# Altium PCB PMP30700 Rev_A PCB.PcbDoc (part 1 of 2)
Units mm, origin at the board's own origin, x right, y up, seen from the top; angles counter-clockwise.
Board outline 118.11 x 43.81 mm, 4 copper layers (Top Layer, Layer 1, Layer 2, Bottom Layer), stack 1.786 mm thick; 113 components, 51 nets, 253 pads, 184 vias.
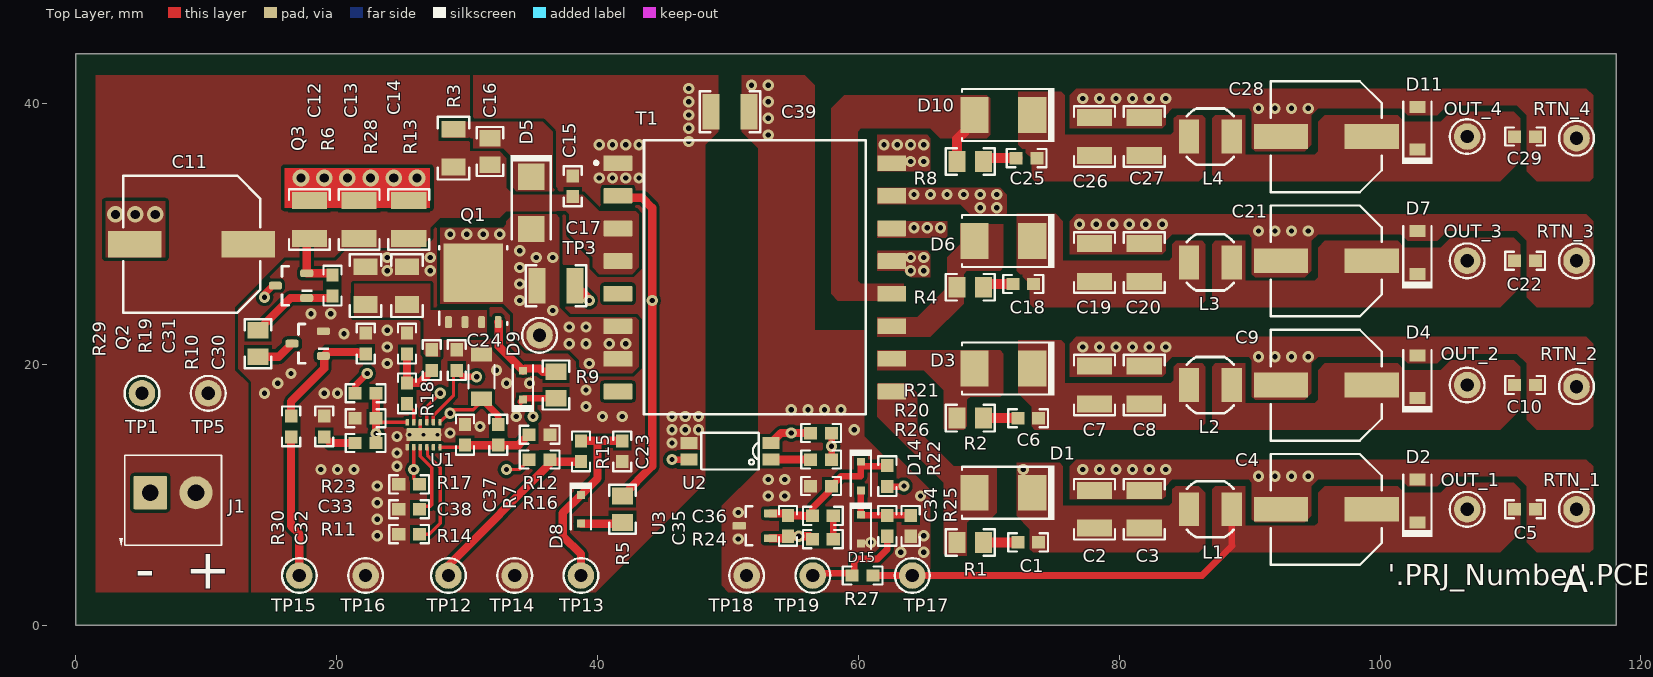
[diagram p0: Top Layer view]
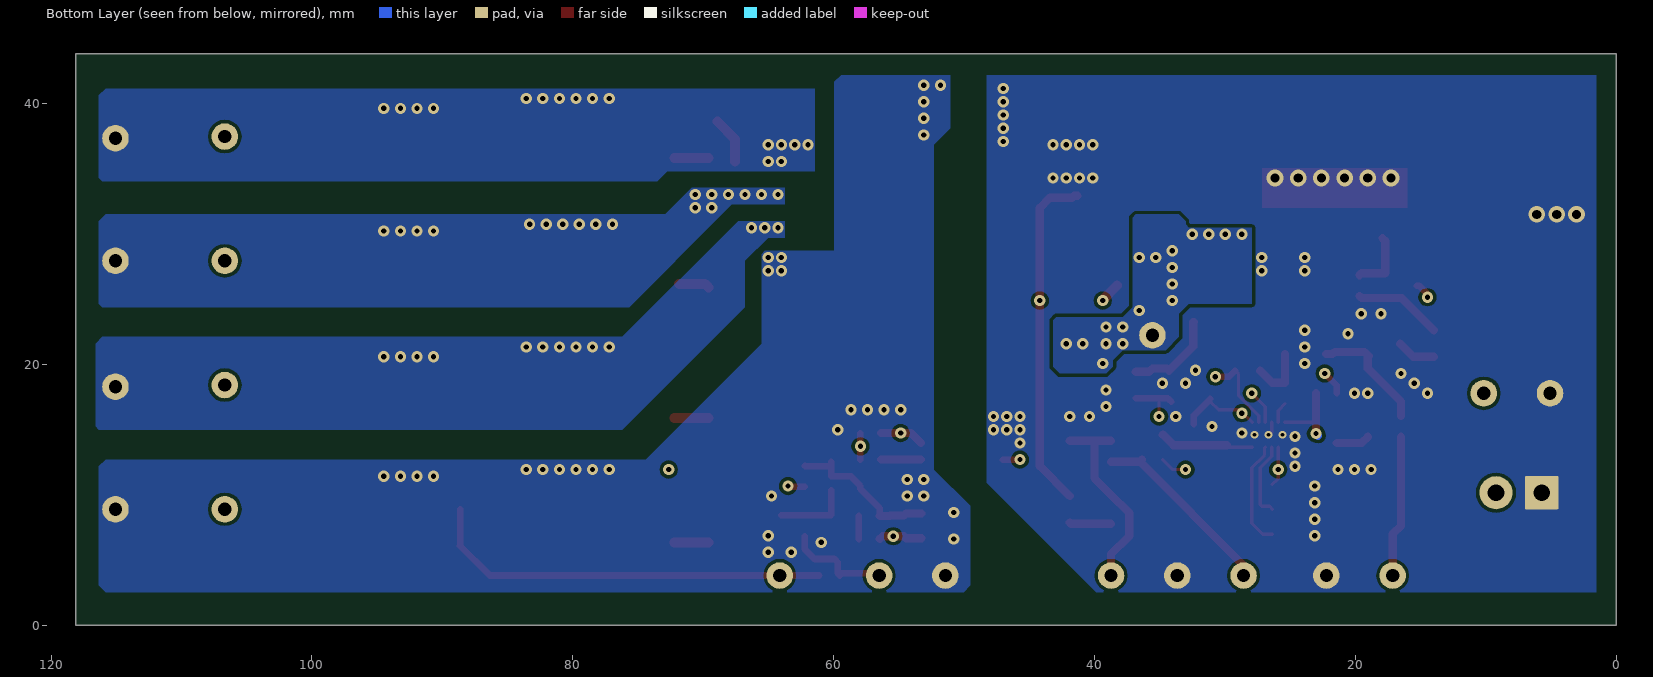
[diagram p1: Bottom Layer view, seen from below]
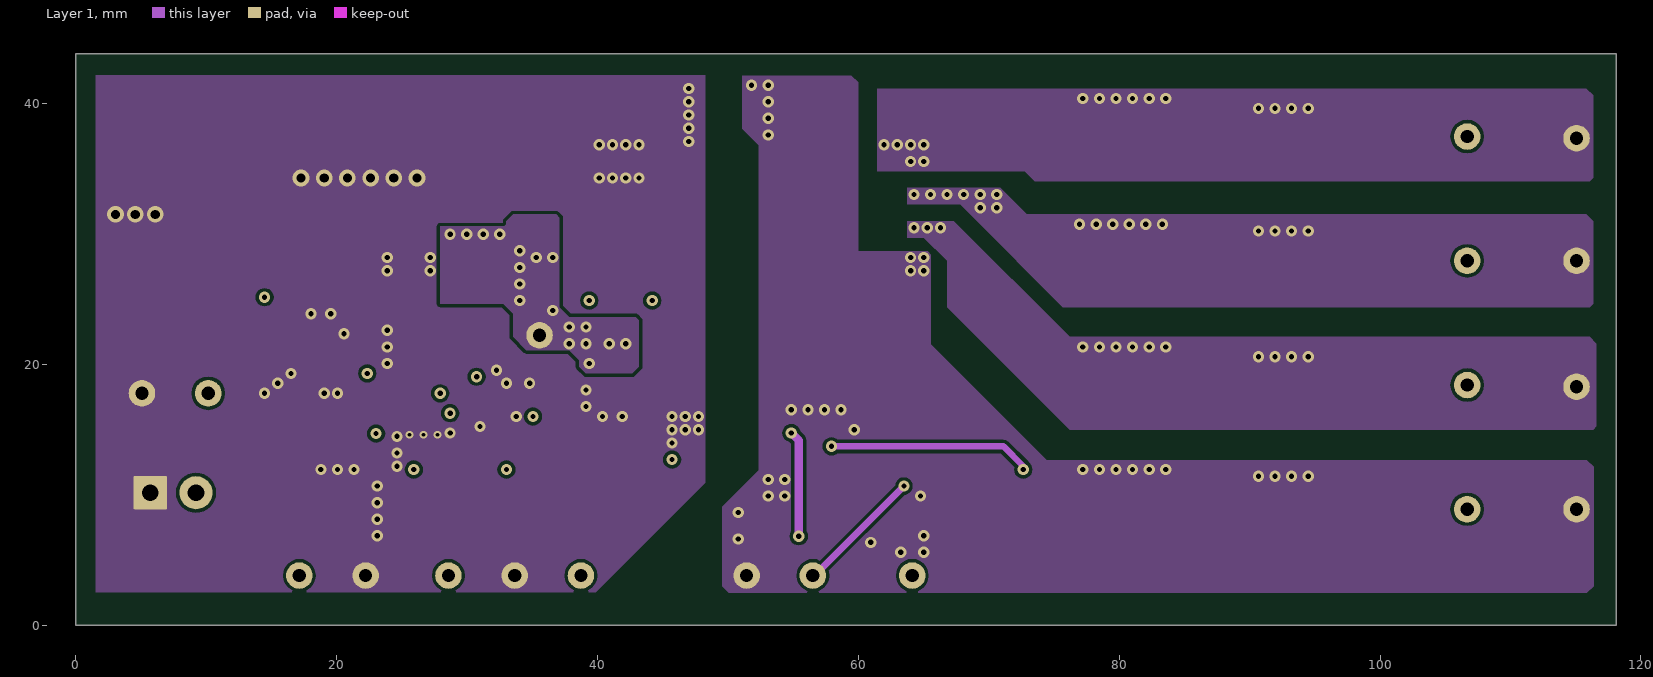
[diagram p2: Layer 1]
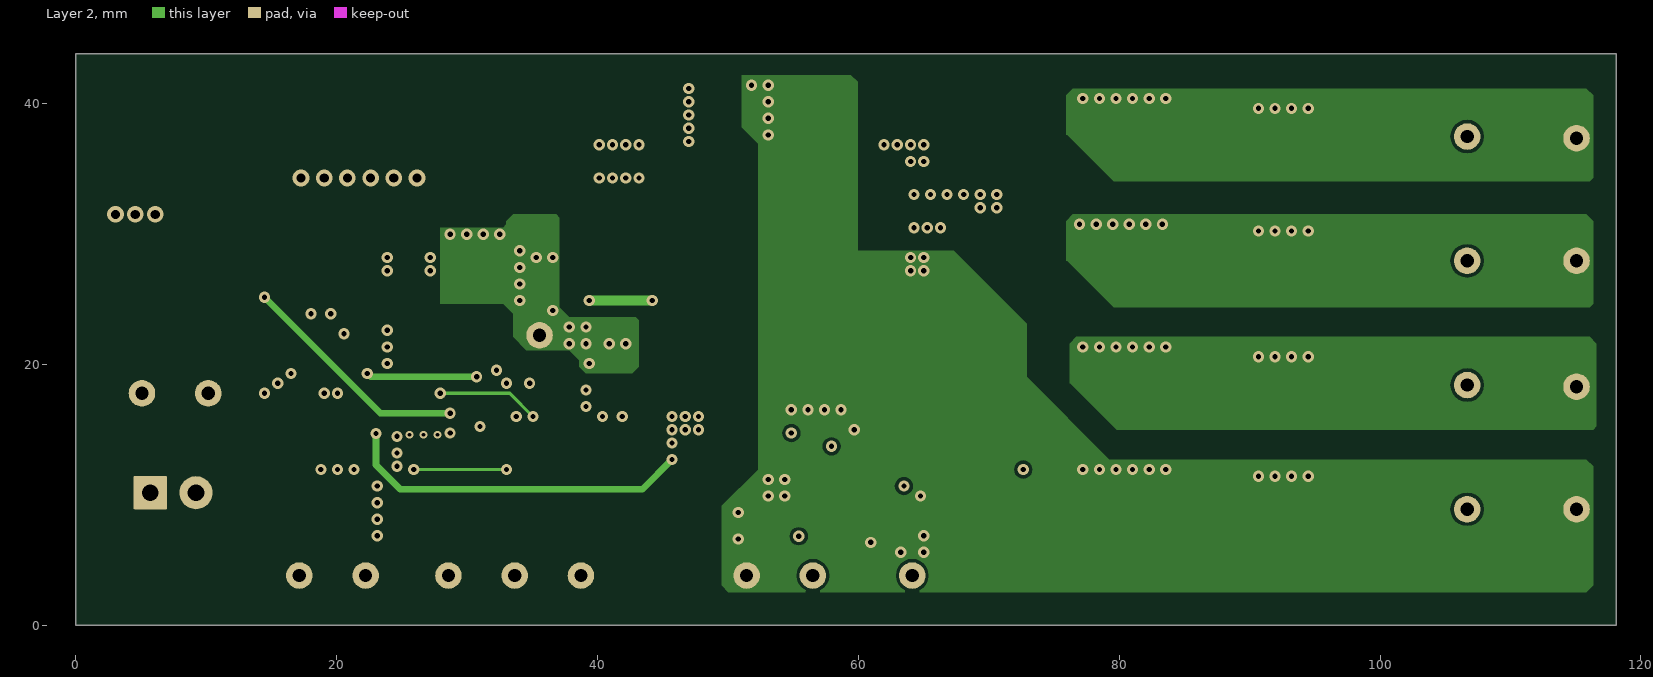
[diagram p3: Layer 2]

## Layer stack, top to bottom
Top Solder: solder mask 0.0102, Solder Resist, Dk 3.5
Top Layer: signal copper 0.035
Dielectric 1: prepreg 0.0711, PP-006, Dk 4.1
Layer 1: signal copper 0.035
Dielectric1: core 1.5037, FR-4, Dk 4.8
Layer 2: signal copper 0.035
Dielectric 2: prepreg 0.0711, PP-006, Dk 4.1
Bottom Layer: signal copper 0.035
Bottom Solder: solder mask 0.0102, Solder Resist, Dk 3.5

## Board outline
0,0 118.11,0 118.11,43.815 0,43.815

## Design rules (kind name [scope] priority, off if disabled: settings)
AcuteAngle [All] p1: minimum=4.50000000000000E+0001 checktracksonly=FALSE
AssemblyTestPointUsage [All] p1: valid=2
BoardOutlineClearance BoardOutlineClearance_MountingHoles [OnCopper and InComponentClass('Mounting Holes')] p1: gap=1.016 ignorepadtopadclearanceinfootprint=FALSE
BoardOutlineClearance BoardOutlineClearance_Poly [OnCopper and IsPoly] p2: gap=0.635 ignorepadtopadclearanceinfootprint=FALSE
BoardOutlineClearance [OnCopper and Not InComponentClass('Logo') and not InComponentClass('FiducialMark') and not InRegion(1000,500,4000,800) and not InPoly] p3: gap=1.905 ignorepadtopadclearanceinfootprint=FALSE
Clearance Clearance_Keepouts [((IsTrack Or IsArc) And Not InPoly) And IsFree and IsKeepOut vs ((IsTrack Or IsArc) And Not InPoly) And IsFree and IsKeepOut] p1: gap=0 ignorepadtopadclearanceinfootprint=FALSE
Clearance Clearance_Poly [InPolygon] p2: gap=0.254 ignorepadtopadclearanceinfootprint=FALSE
Clearance Clearance_FiducialMark [IsKeepOut and InComponentClass('FiducialMark') vs IsPad and InComponentClass('FiducialMark')] p3: gap=0 ignorepadtopadclearanceinfootprint=FALSE
Clearance [All] p4: gap=0.2 ignorepadtopadclearanceinfootprint=FALSE except(0: Arc-Hole Track-Hole SMDPad-Hole THPad-Hole Via-Hole Fill-Hole Poly-Hole Region-Hole Text-Hole)
ComponentClearance ComponentClearance_MountingHoles_FiducialMarks [InComponentClass('Mounting Holes') vs InComponentClass('FiducialMark')] p1: gap=1.27 collisioncheckmode=3 verticalgap=0.254 showdistances=FALSE
ComponentClearance ComponentClearance_Shunt [InComponentClass('Header') vs InComponentClass('Shunt')] p2: gap=0 collisioncheckmode=3 verticalgap=0 showdistances=FALSE
ComponentClearance ComponentClearance_Logo [InComponentClass('Logo')] p3: gap=1.27 collisioncheckmode=3 verticalgap=0.254 showdistances=FALSE
ComponentClearance ComponentClearance_ScrewToNut [(HasFootprint('NY PMS 440 0025 PH')) vs (HasFootprint('Keystone_1902C'))] p4: gap=0.127 collisioncheckmode=3 verticalgap=0.254 showdistances=FALSE
ComponentClearance ComponentClearance_MountingHoles [InComponentClass('Mounting Holes')] p5: gap=6.35 collisioncheckmode=3 verticalgap=2540 showdistances=FALSE
ComponentClearance ComponentClearance_SmallPassives [HasFootprint('0201*') or HasFootprint('0402*') or HasFootprint('0508') or HasFootprint('0603*') or HasFootprint('0612') or HasFootprint('0805*') or HasFootprint('0815*') or HasFootprint('0830*') or HasFootprint('1206*') or HasFootprint('1210*') or HasFootprint('1808*') or HasFootprint('1812*') or HasFootprint('1825*') or HasFootprint('2010*') or HasFootprint('2220*') or HasFootprint('2225*') or HasFootprint('2512*') or HasFootprint('2728*') or HasFootprint('3518*') vs HasFootprint('0201*') or HasFootprint('0402*') or HasFootprint('0508') or HasFootprint('0603*') or HasFootprint('0612') or HasFootprint('0805*') or HasFootprint('0815*') or HasFootprint('0830*') or HasFootprint('1206*') or HasFootprint('1210*') or HasFootprint('1808*') or HasFootprint('1812*') or HasFootprint('1825*') or HasFootprint('2010*') or HasFootprint('2220*') or HasFootprint('2225*') or HasFootprint('2512*') or HasFootprint('2728*') or HasFootprint('3518*')] p6: gap=0.38 collisioncheckmode=3 verticalgap=0.254 showdistances=FALSE
ComponentClearance ComponentClearance_THtoSMT [IsThruComponent vs IsSMTComponent] p7: gap=1.016 collisioncheckmode=3 verticalgap=0.762 showdistances=FALSE
ComponentClearance ComponentClearance_THtoTH [IsThruComponent vs IsThruComponent] p8: gap=0.762 collisioncheckmode=3 verticalgap=0.762 showdistances=FALSE
ComponentClearance [All] p9: gap=0.762 collisioncheckmode=3 verticalgap=0.254 showdistances=FALSE
DiffPairsRouting [All] p1: maxlimit=2.54 minlimit=0.254 mostfreqgap=0.254 toplayer_minwidth=0.381 toplayer_maxwidth=0.381 toplayer_prefwidth=0.381 midlayer1_minwidth=0.381 midlayer1_maxwidth=0.381 midlayer1_prefwidth=0.381 midlayer2_minwidth=0.381 midlayer2_maxwidth=0.381 midlayer2_prefwidth=0.381 bottomlayer_minwidth=0.381 bottomlayer_maxwidth=0.381 bottomlayer_prefwidth=0.381 maxuncoupledlength=25.4
FabricationTestPointUsage TestPointUsage [All] p1: valid=2 allowmultiple=FALSE
FabricationTestpoint Testpoint [All] p1: side=3 testpointundercomponent=TRUE minsize=1.016 maxsize=2.54 preferedsize=1.524 minholesize=0 maxholesize=1.016 preferedholesize=0.813 testpointgrid=0.025 allowsidetop=TRUE allowsidebottom=TRUE usegrid=TRUE gridtolerance=0
FanoutControl Fanout_LCC [IsLCC] p1: bgadir=Out bgaviamode=Centered fanoutstyle=Auto fanoutdirection=Alternating viagrid=0.025 // Fanout_LCC (Default Rule)
FanoutControl Fanout_BGA [IsBGA] p2: bgadir=Out bgaviamode=Centered fanoutstyle=Auto fanoutdirection=Alternating viagrid=0.025 // Fanout_BGA (Default Rule)
FanoutControl Fanout_Default [All] p4: bgadir=Out bgaviamode=Centered fanoutstyle=Auto fanoutdirection=Alternating viagrid=0.025 // Fanout_Default (Default Rule)
FanoutControl Fanout_Small [(CompPinCount < 5)] p5: bgadir=Out bgaviamode=Centered fanoutstyle=Auto fanoutdirection=OutThenIn viagrid=0.025 // Fanout_Small (Default Rule)
HoleSize [All] p1: absolutevalues=TRUE maxlimit=6.375 minlimit=0.3 maxpercent=80.000 minpercent=20.000
MinimumAnnularRing MinimumAnnularRing_ThermalPadVias [IsVia and InAnyComponent] p1: minimumring=0.15
MinimumAnnularRing [All] p2: minimumring=0.203
MinimumSolderMaskSliver MinimumSolderMaskSliver_Logo [InComponentClass('Logo') vs InComponentClass('Logo')] p1: minsoldermaskwidth=0.018
MinimumSolderMaskSliver [All] p2: minsoldermaskwidth=0.1
PlaneConnect [All] p1: planeconnectstyle=Relief reliefexpansion=0.254 reliefentries=4 reliefconductorwidth=0.254 reliefairgap=0.254
PolygonConnect [All] p1: connectstyle=Direct reliefconductorwidth=0.254 reliefentries=4 polygonreliefangle="90 Angle" airgapwidth=0.254
RoutingVias ThermalPadVias [IsVia and InAnyComponent] p1: holewidth=0.3 width=0.5 viastyle="Through Hole" minholewidth=0.3 minwidth=0.6 maxholewidth=0.5 maxwidth=1
RoutingVias [All] p2: holewidth=0.5 width=0.9 viastyle="Through Hole" minholewidth=0.3 minwidth=0.6 maxholewidth=1.016 maxwidth=1.651
SilkToBoardRegionClearance [Not ((IsComment or IsDesignator) And (Hide <> 'False')) and not InRegion(1000,500,4000,800)] p1:
SilkToSilkClearance SilkToSilkClearance_Pb-FreeLogo [(HasFootprint('Pb-Free_Overlay_Medium') OR HasFootprint('Pb-Free_Overlay_Small')) vs (HasFootprint('Pb-Free_Overlay_Medium') OR HasFootprint('Pb-Free_Overlay_Small'))] p1: silktosilkclearance=0
SilkToSilkClearance [All] p2: silktosilkclearance=0.102
SilkToSolderMaskClearance SilkToComponentPadClearance [(IsPad or IsFill or IsRegion) and InAnycomponent] p1: minsilkscreentomaskgap=0.127 clearancetoexposedcopper=TRUE
SilkToSolderMaskClearance "Silk to Solder Mask Opening" [All] p2: minsilkscreentomaskgap=0.102 clearancetoexposedcopper=FALSE
SolderMaskExpansion [All] p1: expansion=0.05
Width [All] p1: maxlimit=2.54 minlimit=0.152 preferedwidth=0.254 checkconnectedcopper=TRUE
15 further rules are at their usual default settings.

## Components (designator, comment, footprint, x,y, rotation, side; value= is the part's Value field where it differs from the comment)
C1 "GRM188R72A471KA01D" 0603 73.025,6.35 r180 top value=470pF
C2 "GRM32ER71H106KA12L" 1210_270 78.105,8.89 r90 top value=10uF
C3 "GRM32ER71H106KA12L" 1210_270 81.915,8.89 r90 top value=10uF
C4 "25SVPF100M" SVPF_E7 95.885,8.89 r180 top value=100uF
C5 "GCM188R71H104KA57D" 0603 111.125,8.89 r0 top value=0.1uF
C6 "GRM188R72A471KA01D" 0603 73.025,15.875 r180 top value=470pF
C7 "GRM32ER71H106KA12L" 1210_270 78.105,18.415 r90 top value=10uF
C8 "GRM32ER71H106KA12L" 1210_270 81.915,18.415 r90 top value=10uF
C9 "25SVPF100M" SVPF_E7 95.885,18.415 r180 top value=100uF
C10 "GCM188R71H104KA57D" 0603 111.125,18.415 r0 top value=0.1uF
C11 "EEH-ZC1H101P" Panasonic_G 8.89,29.21 r180 top value=100uF
C12 "GRM32ER71H106KA12L" 1210_270 17.915,31.115 r90 top value=10uF
C13 "GRM32ER71H106KA12L" 1210_270 21.725,31.115 r90 top value=10uF
C14 "GRM32ER71H106KA12L" 1210_270 25.535,31.115 r90 top value=10uF
C15 "GCM188R71H104KA57D" 0603 38.1,33.655 r90 top value=0.1uF
C16 "GRM21BR72A103MA01L" 0805_HV 31.75,36.322 r90 top value=0.01uF
C17 "GRM32ER71H106KA12L" 1210_270 36.83,26.035 r0 top value=10uF
C18 "GRM188R72A471KA01D" 0603 72.644,26.162 r180 top value=470pF
C19 "GRM32ER71H106KA12L" 1210_270 78.105,27.813 r90 top value=10uF
C20 "GRM32ER71H106KA12L" 1210_270 81.915,27.813 r90 top value=10uF
C21 "25SVPF100M" SVPF_E7 95.885,27.94 r180 top value=100uF
C22 "GCM188R71H104KA57D" 0603 111.125,27.94 r0 top value=0.1uF
C23 "GRM188R71E105KA12D" 0603 41.91,13.335 r270 top value=1uF
C24 "C3216X7S2A335M160AB" 1206_190 31.115,19.05 r90 top value=3.3uF
C25 "GRM188R72A471KA01D" 0603 72.898,35.814 r180 top value=470pF
C26 "GRM32ER71H106KA12L" 1210_270 78.105,37.465 r90 top value=10uF
C27 "GRM32ER71H106KA12L" 1210_270 81.915,37.465 r90 top value=10uF
C28 "25SVPF100M" SVPF_E7 95.885,37.465 r180 top value=100uF
C29 "GCM188R71H104KA57D" 0603 111.125,37.465 r0 top value=0.1uF
C30 "GRM188R71E105KA12D" 0603 29.21,20.32 r90 top value=1uF
C31 "GRM188R71H221KA01D" 0603 25.4,21.59 r90 top value=220pF
C32 "06033C473JAT2A" 0603 19.05,15.24 r90 top value=0.047uF
C33 "GRM1885C1H471JA01D" 0603 22.225,15.875 r180 top value=470pF
C34 "06033C473JAT2A" 0603 62.23,7.62 r90 top value=0.047uF
C35 "GRM1885C1H471JA01D" 0603 54.61,7.62 r90 top value=470pF
C36 "06033C473JAT2A" 0603 57.277,8.382 r180 top value=0.047uF
C37 "GRM1885C1H471JA01D" 0603 29.845,14.605 r90 top value=470pF
C38 "GCM188R71H104KA57D" 0603 25.565,8.89 r180 top value=0.1uF
C39 "VJ1210Y102KXEAT5Z" 1210 50.165,39.37 r180 top value=1000pF
D1 "STPS3150U" SMB 71.12,10.16 r180 top
D2 "MMSZ5245B-7-F" SOD-123 102.87,9.525 r90 top value=15V
D3 "STPS3150U" SMB 71.12,19.685 r180 top
D4 "MMSZ5245B-7-F" SOD-123 102.87,19.05 r90 top value=15V
D5 "MBRA1H1000T3G" SMA 34.925,32.385 r270 top value=MBRA1H100T3G
D6 "STPS3150U" SMB 71.12,29.464 r180 top
D7 "MMSZ5245B-7-F" SOD-123 102.87,28.575 r90 top value=15V
D8 "PMEG6010CEJ,115" SOD-323F 38.735,8.89 r270 top value=PMEG6010
D9 "PMEG6010CEJ,115" SOD-323F 34.29,18.415 r90 top value=PMEG6010
D10 "STPS3150U" SMB 71.12,39.116 r180 top
D11 "MMSZ5245B-7-F" SOD-123 102.87,38.1 r90 top value=15V
D14 "MMDL914-TP" SOD-323 60.198,11.43 r270 top value=100V
D15 "MMDL914-TP" SOD-323 60.198,7.366 r270 top value=100V
J1 "ED555/2DS" TERM_BLK_ED555-2DS 5.715,10.16 r0 top
L1 "SD43-472MLB" SD43 86.995,8.89 r0 top value=4.7uH
L2 "SD43-472MLB" SD43 86.995,18.415 r0 top value=4.7uH
L3 "SD43-472MLB" SD43 86.995,27.813 r0 top value=4.7uH
L4 "SD43-472MLB" SD43 86.995,37.465 r0 top value=4.7uH
OUT_1 "5000" Keystone5000 106.68,8.89 r0 top
OUT_2 "5000" Keystone5000 106.68,18.415 r0 top
OUT_3 "5000" Keystone5000 106.68,27.94 r0 top
OUT_4 "5000" Keystone5000 106.68,37.465 r0 top
Q1 "CSD18537NQ5A" DQJ0008A 30.48,26.035 r90 top value=60V
Q2 "MMBT3904" SOT-23 17.78,21.59 r180 top value="40 V"
Q3 "MMBT3906" SOT-23 16.51,26.035 r180 top value="40 V"
R1 "ERJ-P6WF10R0V" 0805_HV 68.58,6.35 r0 top value=10.0
R2 "ERJ-P6WF10R0V" 0805_HV 68.58,15.875 r0 top value=10.0
R3 "CRCW1206100KJNEA" 1206 28.956,36.576 r270 top value=100k
R4 "ERJ-P6WF10R0V" 0805_HV 68.58,25.908 r0 top value=10.0
R5 "CRCW08054R70JNEA" 0805_HV 41.91,8.89 r90 top value=4.7
R6 "CRCW0603100KFKEA" 0603 19.685,26.035 r270 top value=100k
R7 "CRCW060360K4FKEA" 0603 32.385,14.605 r90 top value=60.4k
R8 "ERJ-P6WF10R0V" 0805_HV 68.58,35.56 r0 top value=10.0
R9 "CRCW08054R70JNEA" 0805_HV 36.83,18.415 r270 top value=4.7
R10 "CRCW0603100RFKEA" 0603 27.305,20.32 r90 top value=100
R11 "CRCW060310K0FKEA" 0603 22.225,13.97 r0 top value=10.0k
R12 "CRCW060320K0FKEA" 0603 35.56,14.605 r180 top value=20.0k
R13 "CSR1206FK20L0" 1206 25.4,26.035 r270 top value=0.02
R14 "CRCW060343K2FKEA" 0603 25.565,6.985 r0 top value=43.2k
R15 "CRCW060349R9FKEA" 0603 38.735,13.335 r90 top value=49.9
R16 "CRCW06036K04FKEA" 0603 35.56,12.7 r0 top value=6.04k
R17 "CRCW06031K00FKEA" 0603 25.565,10.795 r0 top value=1.00k
R18 "CRCW0603100RFKEA" 0603 25.4,17.78 r90 top value=100
R19 "CRCW0603100KFKEA" 0603 22.225,21.59 r270 top value=100k
R20 "CRCW06031K00FKEA" 0603 57.15,12.7 r0 top value=1.00k
R21 "RC0603FR-073K32L" 0603 57.15,14.732 r0 top value=3.32k
R22 "CRCW060315K0FKEA" 0603 62.23,11.43 r270 top value=15.0k
R23 "RC0603FR-073K32L" 0603 22.225,17.78 r0 top value=3.32k
R24 "CRCW060310K0FKEA" 0603 57.277,6.604 r0 top value=10.0k
R25 "CRCW0603100KFKEA" 0603 64.008,7.62 r90 top value=100k
R26 "RC0603FR-073K32L" 0603 57.15,10.668 r0 top value=3.32k
R27 "CRCW060349R9FKEA" 0603 60.325,3.81 r0 top value=49.9
R28 "CSR1206FK20L0" 1206 22.225,26.035 r270 top value=0.02
R29 "ERJ-6GEYJ333V" 0805_HV 13.97,21.59 r90 top value=33k
R30 "CRCW0603100KFKEA" 0603 16.51,15.24 r270 top value=100k
RTN_1 "5001" Keystone5001 115.062,8.89 r0 top
RTN_2 "5001" Keystone5001 115.062,18.288 r0 top
RTN_3 "5001" Keystone5001 115.062,27.94 r0 top
RTN_4 "5001" Keystone5001 115.062,37.338 r0 top
T1 "B180179-X0-D5577-V0" FP-B180179-X0-D5577-V0_TRANSFORMER_SMD_16-MFG 52.07,26.67 r180 top
TP1 "5001" Keystone5001 5.08,17.78 r0 top
TP3 "5002" Keystone5002 35.56,22.225 r90 top
TP5 "5000" Keystone5000 10.16,17.78 r90 top
TP12 "5003" Keystone5003 28.575,3.81 r90 top
TP13 "5000" Keystone5000 38.735,3.81 r90 top
TP14 "5001" Keystone5001 33.655,3.81 r90 top
TP15 "5000" Keystone5000 17.145,3.81 r90 top
TP16 "5001" Keystone5001 22.225,3.81 r90 top
TP17 "5000" Keystone5000 64.135,3.81 r90 top
TP18 "5001" Keystone5001 51.435,3.81 r90 top
TP19 "5003" Keystone5003 56.515,3.81 r90 top
U1 "LM51551QDSSTQ1" DSS0012C 26.67,14.605 r270 top
U2 "TCMT1107" SOP-4 50.165,13.335 r180 top
U3 "TL431AQDBZRQ1" DBZ0003A_N 52.07,7.62 r180 top

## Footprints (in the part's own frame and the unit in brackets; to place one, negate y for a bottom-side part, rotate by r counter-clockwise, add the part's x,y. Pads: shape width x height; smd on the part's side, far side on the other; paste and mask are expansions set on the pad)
0603 [mm] "0603 from SM-752 data"
  rect 1x0.95 smd: 1(-0.8,0) 2(0.8,0)
  silkscreen extent -1.52,-0.69 1.52,0.69, body extent -0.87,-0.47 0.87,0.47, height 1
0805_HV [mil] "0805 with 30mil clearance between pads"
  rect 50x63 smd: 1(-40,0) 2(40,0)
  silkscreen extent -74,-40 74,40, body extent -43,-29 43,29, height 57
1206 [mm] "1206 from SM-752 data"
  rect 1.3x1.85 smd: 1(-1.45,0) 2(1.45,0)
  silkscreen extent -2.4,-1.21 2.4,1.21, body extent -1.7,-0.9 1.7,0.9, height 1.35
1206_190 [mm] "1206_190"
  rect 1.1x1.6 smd: 1(-1.7,0) 2(1.7,0)
  silkscreen extent -0.9,-1 0.9,1, body extent -1.75,-0.95 1.75,0.95, height 1.9
1210 [mm] "1210 from SM-752 data"
  rect 1.3x2.7 smd: 1(-1.45,0) 2(1.45,0)
  silkscreen extent -2.32,-1.57 2.32,1.57, body extent -1.7,-1.35 1.7,1.35, height 1.35
1210_270 [mm] "1210"
  rect 1.3x2.7 smd: 1(-1.45,0) 2(1.45,0)
  silkscreen extent -2.32,-1.57 2.32,1.57, body extent -1.7,-1.35 1.7,1.35, height 2.7
DBZ0003A_N [mm] "SOT23, 3-Leads, Body 2.9x1.3mm, Pitch 0.95mm, Lead Span 2.4mm, IPC Medium Density"
  rrect17% 1x0.6 smd: 1(-1.2,0.95) 2(-1.2,-0.95) 3(1.2,0)
  silkscreen extent 0.2,-1.5 0.7,1.5, body extent -1.26,-1.46 1.26,1.46, height 0.98
DQJ0008A [mm] "SMD, 8-Leads, Body 5.75x4.9mm"
  rrect39% 0.91x0.51 smd paste-0.05 mask-0.05: 1(-2.795,1.905) 2(-2.795,0.635) 3(-2.795,-0.635) 4(-2.795,-1.905) 5(2.795,-1.905) 6(2.795,-0.635) 7(2.795,0.635) 8(2.795,1.905)
  rrect8% 1.58x1.25 on Top Paste: 9(-0.38,1.45) 9(-0.38,0) 9(-0.38,-1.45) 9(1.4,-1.45) 9(1.4,0) 9(1.4,1.45)
  rrect3% 3.48x4.47 on Top Solder: 9(0.55,0)
  rrect2% 4.49x4.57 smd paste-2.5 mask-2.5: 9(1.005,0)
  silkscreen extent -3,-2.6 3,2.6, body extent -3.13,-2.45 3.13,2.45, height 1.15
DSS0012C [mm] "WSON-12"
  rrect40% 0.5x0.25 smd: 1(-0.95,1.25) 2(-0.95,0.75) 3(-0.95,0.25) 4(-0.95,-0.25) 5(-0.95,-0.75) 6(-0.95,-1.25) 7(0.95,-1.25) 8(0.95,-0.75) 9(0.95,-0.25) 10(0.95,0.25) 11(0.95,0.75) 12(0.95,1.25)
  rrect11% 0.95x1.17 on Top Paste: 13(0,0.685) 13(0,-0.685)
  rrect11% 1x2.65 smd paste-0.5: 13(0,0)
  body extent -1,-1.5 1,1.5, height 0.81
FP-B180179-X0-D5577-V0_TRANSFORMER_SMD_16-MFG [mm]
  rrect8% 2.2x1.2 smd paste+0 mask+0: 1(10.5,-8.75) 2(10.5,-6.25) 3(10.5,-3.75) 4(10.5,-1.25) 5(10.5,1.25) 6(10.5,3.75) 7(10.5,6.25) 8(10.5,8.75) 9(-10.5,8.75) 10(-10.5,6.25) 11(-10.5,3.75) 12(-10.5,1.25) 13(-10.5,-1.25) 14(-10.5,-3.75) 15(-10.5,-6.25) 16(-10.5,-8.75)
  silkscreen extent -8.5,-10.5 12.3,10.5, body extent -11.7,-10.6 11.7,10.6, height 0.25
Keystone5000 [mil] "For Keystone 500x miniature loop terminals"
  round 80 hole 40: 1(0,0)
  silkscreen extent -52,-52 52,52, body extent -49,-49 49,49, height 182
Keystone5001 [mil] "For Keystone 500x miniature loop terminals"
  round 80 hole 40: 1(0,0)
  silkscreen extent -52,-52 52,52, body extent -49,-49 49,49, height 182
Keystone5002 [mil] "For Keystone 500x miniature loop terminals"
  round 80 hole 40: 1(0,0)
  silkscreen extent -52,-52 52,52, body extent -49,-49 49,49, height 182
Keystone5003 [mil] "For Keystone 500x miniature loop terminals"
  round 80 hole 40: 1(0,0)
  silkscreen extent -52,-52 52,52, body extent -49,-49 49,49, height 182
Panasonic_G [mm] "SMD, 2-Leads, Dia 10mm"
  rect 4.1x2 smd: 1(-4.35,0) 2(4.35,0)
  silkscreen extent -5.25,-5.25 5.25,5.25, body extent -5.25,-5.25 5.25,5.25, height 10.51
SD43 [mm] "COILCRAFT"
  rect 1.55x2.6 smd: 1(-1.64,0) 2(1.64,0)
  silkscreen extent -1.81,-2.16 1.79,2.16, body extent -2.3,-2.1 2.32,2.1, height 3.45
SMA [mm] "Molded Diode, 2-Leads, Body 4.3x2.6mm, IPC Medium Density, based on OnSemi component dimensions and land pattern"
  rect 2x2 smd: 1(-2,0) 2(2,0)
  silkscreen extent -3.66,-1.57 2.79,1.57, body extent -2.6,-1.3 2.6,1.3, height 2.42
SMB [mm] "Molded Diode, 2-Leads, Body 5.4x3.6mm, IPC Medium Density, based on OnSemi component dimensions"
  rect 2.159x2.743 smd: 1(-2.21,0) 2(2.21,0)
  silkscreen extent -3.94,-2.08 3.18,2.08, body extent -2.7,-1.8 2.7,1.8, height 2.32
SOD-123 [mm] "On Semi recommended land pattern"
  rect 0.915x1.22 smd: 1(-1.637,0) 2(1.637,0)
  silkscreen extent -2.74,-1.17 2.03,1.17, body extent -1.93,-0.9 1.93,0.9, height 1.35
SOD-323 [mm] "NXP recommended land pattern"
  rect 0.6x0.6 smd paste-0.05: 1(-1.1,0) 2(1.1,0)
  silkscreen extent -2.06,-0.86 1.53,0.86, body extent -1.3,-0.67 1.3,0.68, height 1.1
SOD-323F [mm] "NXP recommended land pattern"
  rect 0.6x0.6 smd paste-0.05: 1(-1.1,0) 2(1.1,0)
  silkscreen extent -2.06,-0.86 1.53,0.86, body extent -1.35,-0.67 1.35,0.68, height 0.79
SOP-4 [mm] "Vishay Half Pitch Mini-Flat Package"
  rect 1.3x0.9 smd: 1(-3.15,0.635) 2(-3.15,-0.635) 3(3.15,-0.635) 4(3.15,0.635)
  silkscreen extent -2.2,-1.41 2.2,1.39, body extent -3.5,-1.4 3.5,1.4, height 2.12
SOT-23 [mm] "SOT23, 3-Leads, Body 2.9x1.3mm, Pitch 0.95mm, Lead Span 2.5mm, IPC Medium Density"
  rrect50% 1x0.6 smd: 1(-1.2,0.95) 2(-1.2,-0.95) 3(1.2,0)
  silkscreen extent -1.63,-1.5 0.7,1.5, body extent -1.16,-1.45 1.21,1.45, height 1
SVPF_E7 [mm] "Panasonic SVPF series"
  rect 4.15x1.9 smd: 1(-3.475,0) 2(3.475,0)
  silkscreen extent -4.24,-4.24 4.26,4.26, body extent -4.24,-4.24 4.26,4.26, height 7
TERM_BLK_ED555-2DS [mil]
  rrect4% 100x100 hole 50: 1(0,0)
  round 100 hole 50: 2(138,0)
  silkscreen extent -93,-161 215,113, body extent -69,-150 207,106, height 323

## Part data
C1 C6 C18 C25: library part CMP-0007482-4, "CAP, CERM, 470 pF, 100 V, +/- 10%, X7R, 0603", Cap_Case=0603, Manufacturer=MuRata, Supplier Part Number 1=490-1467-1-ND, TempCo=X7R, Tolerance_%=10%, Value1=Unknown, Value2=100V, ValueDisplayed=470pF
C2 C3 C7 C8 C12 C13 C14 C17 C19 C20 C26 C27: library part CMP-0009226-3, "CAP, CERM, 10 uF, 50 V, +/- 10%, X7R, 1210", Cap_Case=1210, Manufacturer=MuRata, Supplier Part Number 1=490-6544-1-ND, TempCo=X7R, Tolerance_%=10%, Value1=Unknown, Value2=50V, ValueDisplayed=10uF
C4 C9 C21 C28: library part CMP-0012117-3, "CAP, Aluminum Polymer, 100 uF, 25 V, +/- 20%, 0.024 ohm, 8.0x7.0mm SMD", Manufacturer=Panasonic, Tolerance_%=20%, Value1="0.024 ohm", Value2=25V, ValueDisplayed=100uF
C5 C10 C15 C22 C29 C38: library part CMP-0007144-4, "CAP, CERM, 0.1 uF, 50 V, +/- 10%, X7R, 0603", Cap_Case=0603, Manufacturer=MuRata, Supplier Part Number 1=490-4779-1-ND, TempCo=X7R, Tolerance_%=10%, Value1="0.02 ohm", Value2=50V, ValueDisplayed=0.1uF
C11: library part CMP-0064994-2, "CAP, Polymer Hybrid, 100 uF, 50 V,+/- 20%, 0.028 ohm, AEC-Q200 Grade 1, D10xL10.2mm SMD", Cap_Case=10x10.2mm, Manufacturer=Panasonic, Supplier Part Number 1=P15462CT-ND, Tolerance_%=20%, Value1="0.028 ohm", Value2=50V, ValueDisplayed=100uF
C16: library part CMP-0008362-2, "CAP, CERM, 0.01 uF, 100 V, +/- 20%, X7R, 0805", Cap_Case=0805, Manufacturer=MuRata, Supplier Part Number 1=490-1653-1-ND, TempCo=X7R, Tolerance_%=20%, Value1=Unknown, Value2=100V, ValueDisplayed=0.01uF
C23 C30: library part CMP-0007405-4, "CAP, CERM, 1 uF, 25 V, +/- 10%, X7R, 0603", Cap_Case=0603, Manufacturer=MuRata, Supplier Part Number 1=490-5307-1-ND, TempCo=X7R, Tolerance_%=10%, Value1=Unknown, Value2=25V, ValueDisplayed=1uF
C24: library part CMP-0008725-2, "CAP, CERM, 3.3 uF, 100 V, +/- 20%, X7S, 1206_190", Cap_Case=1206_190, Manufacturer=TDK, Supplier Part Number 1=445-9234-1-ND, TempCo=X7S, Tolerance_%=20%, Value1="0.003048 ohm", Value2=100V, ValueDisplayed=3.3uF
C31: library part CMP-0007442-5, "CAP, CERM, 220 pF, 50 V, +/- 10%, X7R, 0603", Cap_Case=0603, Manufacturer=MuRata, Supplier Part Number 1=490-1483-1-ND, TempCo=X7R, Tolerance_%=10%, Value1=Unknown, Value2=50V, ValueDisplayed=220pF
C32 C34 C36: library part CMP-0006757-5, "CAP, CERM, 0.047 uF, 25 V, +/- 5%, X7R, 0603", Cap_Case=0603, Manufacturer=AVX, Supplier Part Number 1=478-3716-1-ND, TempCo=X7R, Tolerance_%=5%, Value1="0.052 ohm", Value2=25V, ValueDisplayed=0.047uF
C33 C35 C37: library part CMP-0007221-4, "CAP, CERM, 470 pF, 50 V, +/- 5%, C0G/NP0, 0603", Cap_Case=0603, Manufacturer=MuRata, Supplier Part Number 1=490-1443-1-ND, TempCo=C0G/NP0, Tolerance_%=5%, Value1=Unknown, Value2=50V, ValueDisplayed=470pF
C39: library part CMP-0009270-2, "CAP, CERM, 1000 pF, 500 V, +/- 10%, X7R, 1210", Cap_Case=1210, Manufacturer=Vishay-Vitramon, Supplier Part Number 1=720-1044-1-ND, TempCo=X7R, Tolerance_%=10%, Value1=Unknown, Value2=500V, ValueDisplayed=1000pF
D1 D3 D6 D10: library part CMP-0028766-2, "Diode, Schottky, 150 V, 3 A, SMB", Manufacturer=STMicroelectronics, Value1=3A, Value2=0.67V
D2 D4 D7 D11: library part CMP-0005753-4, "Diode, Zener, 15 V, 500 mW, SOD-123", Manufacturer="Diodes Inc.", Power_W=500mW, Value1=0.5W
D5: library part CMP-0028550-2, "Diode, Schottky, 40 V, 1 A, SMA", Manufacturer="ON Semiconductor", PartNumber=MBRA1H100T3G, Value1=1A, Value2=0.55V
D8 D9: library part CMP-0077011-2, "Diode, Schottky, 60 V, 1 A, SOD-323F", Manufacturer=Nexperia, Value1=1A, Value2=0.66V
D14 D15: library part CMP-0029045-2, "Diode, Switching, 100 V, 0.2 A, SOD-323", Manufacturer="Micro Commercial Components", Value1=0.2A, Value2=1V
J1: library part CMP-0074913-1, "Terminal Block, 3.5mm Pitch, 2x1, TH", Color=Grey, Current_A=6A, Manufacturer="On-Shore Technology", Supplier Part Number 1=ED1514-ND, Voltage_V=150V
L1 L2 L3 L4: library part CMP-0060747-1, "Inductor, Ferrite, 4.7 uH, 2.9 A, 0.094 ohm, SMD", Manufacturer=Coilcraft, Value1="0.094 ohm", Value2=2.9A, ValueDisplayed=4.7uH
OUT_1 OUT_2 OUT_3 OUT_4 TP5 TP13 TP15 TP17: library part CMP-0055137-1, "Test Point, Miniature, Red, TH", Color=Red, Manufacturer=Keystone, Supplier Part Number 1=36-5000-ND
Q1: library part CMP-0000822-1, "MOSFET, N-CH, 60 V, 50 A, DQJ0008A (VSONP-8)", Alternate Manufacturer=None, Manufacturer="Texas Instruments", Supplier Part Number 1=296-36455-1-ND, Value1=0.03, Value2="14 nC"
Q2: library part CMP-0000386-1, "Transistor, NPN, 40 V, 0.2 A, SOT-23", Manufacturer="Fairchild Semiconductor", Supplier Part Number 1=MMBT3904FSCT-ND, Value1="0.2 A", Value2=300
Q3: library part CMP-0000325-2, "Transistor, PNP, 40 V, 0.2 A, SOT-23", Manufacturer="Fairchild Semiconductor", Supplier Part Number 1=MMBT3906FSCT-ND, Value1="0.2 A", Value2=300
R1 R2 R4 R8: library part CMP-0065342-2, "RES, 10.0, 1%, .5 W, AEC-Q200 Grade 0, 0805", Manufacturer=Panasonic, Power_W=500mW, Supplier Part Number 1=P16861CT-ND, TempCo="200 ppm/C", Tolerance_%=1%, Value2=.5W, Value_Code=10R0, ValueDisplayed=10.0
R3: library part CMP-0018574-2, "RES, 100 k, 5%, 0.25 W, 1206", Manufacturer=Vishay-Dale, Power_W=250mW, Supplier Part Number 1=541-100KECT-ND, TempCo="200 ppm/C", Tolerance_%=5%, Value2=0.25W, Value_Code=100k
R5 R9: library part CMP-0020563-2, "RES, 4.7, 5%, 0.125 W, 0805", Manufacturer=Vishay-Dale, Power_W=125mW, Supplier Part Number 1=541-4.7ACT-ND, TempCo="200 ppm/C", Tolerance_%=5%, Value2=0.125W, Value_Code=4R70, ValueDisplayed=4.7
R6 R19 R25 R30: library part CMP-0021990-4, "RES, 100 k, 1%, 0.1 W, AEC-Q200 Grade 0, 0603", Manufacturer=Vishay-Dale, Power_W=100mW, Supplier Part Number 1=541-100KHCT-ND, TempCo="100 ppm/C", Tolerance_%=1%, Value2=0.1W, Value_Code=100k
R7: library part CMP-0022532-4, "RES, 60.4 k, 1%, 0.1 W, AEC-Q200 Grade 0, 0603", Manufacturer=Vishay-Dale, Power_W=100mW, Supplier Part Number 1=541-60.4KHCT-ND, TempCo="100 ppm/C", Tolerance_%=1%, Value2=0.1W, Value_Code=60k4, ValueDisplayed=60.4k
R10 R18: library part CMP-0021991-3, "RES, 100, 1%, 0.1 W, 0603", Manufacturer=Vishay-Dale, Power_W=100mW, Supplier Part Number 1=541-100HCT-ND, TempCo="100 ppm/C", Tolerance_%=1%, Value2=0.1W, Value_Code=100R, ValueDisplayed=100
R11 R24: library part CMP-0021998-3, "RES, 10.0 k, 1%, 0.1 W, 0603", Manufacturer=Vishay-Dale, Power_W=100mW, Supplier Part Number 1=541-10.0KHCT-ND, TempCo="100 ppm/C", Tolerance_%=1%, Value2=0.1W, Value_Code=10k0, ValueDisplayed=10.0k
R12: library part CMP-0022204-4, "RES, 20.0 k, 1%, 0.1 W, AEC-Q200 Grade 0, 0603", Manufacturer=Vishay-Dale, Power_W=100mW, Supplier Part Number 1=541-20.0KHCT-ND, TempCo="100 ppm/C", Tolerance_%=1%, Value2=0.1W, Value_Code=20k0, ValueDisplayed=20.0k
R13 R28: library part CMP-0017260-2, "RES, 0.02, 1%, 0.5 W, 1206", Manufacturer="Stackpole Electronics Inc", Power_W=500mW, Supplier Part Number 1=CSR1206FK20L0CT-ND, TempCo="100 ppm/C", Tolerance_%=1%, Value2=0.5W, Value_Code=R020, ValueDisplayed=0.02
R14: library part CMP-0022422-4, "RES, 43.2 k, 1%, 0.1 W, AEC-Q200 Grade 0, 0603", Manufacturer=Vishay-Dale, Power_W=100mW, Supplier Part Number 1=541-43.2KHCT-ND, TempCo="100 ppm/C", Tolerance_%=1%, Value2=0.1W, Value_Code=43k2, ValueDisplayed=43.2k
R15 R27: library part CMP-0022448-3, "RES, 49.9, 1%, 0.1 W, 0603", Manufacturer=Vishay-Dale, Power_W=100mW, Supplier Part Number 1=541-49.9HCT-ND, TempCo="100 ppm/C", Tolerance_%=1%, Value2=0.1W, Value_Code=49R9, ValueDisplayed=49.9
R16: library part CMP-0022558-4, "RES, 6.04 k, 1%, 0.1 W, AEC-Q200 Grade 0, 0603", Manufacturer=Vishay-Dale, Power_W=100mW, Supplier Part Number 1=541-6.04KHCT-ND, TempCo="100 ppm/C", Tolerance_%=1%, Value2=0.1W, Value_Code=6k04, ValueDisplayed=6.04k
R17 R20: library part CMP-0022109-4, "RES, 1.00 k, 1%, 0.1 W, 0603", Manufacturer=Vishay-Dale, Power_W=100mW, Supplier Part Number 1=541-1.00KHCT-ND, TempCo="100 ppm/C", Tolerance_%=1%, Value2=0.1W, Value_Code=1k00, ValueDisplayed=1.00k
R21 R23 R26: library part CMP-0023080-5, "RES, 3.32 k, 1%, 0.1 W, 0603", Manufacturer=Yageo, Power_W=100mW, Supplier Part Number 1=311-3.32KHRCT-ND, TempCo="100 ppm/C", Tolerance_%=1%, Value2=0.1W, Value_Code=3k32, ValueDisplayed=3.32k
R22: library part CMP-0022066-4, "RES, 15.0 k, 1%, 0.1 W, AEC-Q200 Grade 0, 0603", Manufacturer=Vishay-Dale, Power_W=100mW, Supplier Part Number 1=541-15.0KHCT-ND, TempCo="100 ppm/C", Tolerance_%=1%, Value2=0.1W, Value_Code=15k0, ValueDisplayed=15.0k
R29: library part CMP-0020705-3, "RES, 33 k, 5%, 0.125 W, AEC-Q200 Grade 0, 0805", Manufacturer=Panasonic, Power_W=125mW, Supplier Part Number 1=P33KACT-ND, TempCo="200 ppm/C", Tolerance_%=5%, Value2=0.125W, Value_Code=33k0, ValueDisplayed=33k
RTN_1 RTN_2 RTN_3 RTN_4 TP1 TP14 TP16 TP18: library part CMP-0055138-1, "Test Point, Miniature, Black, TH", Color=Black, Manufacturer=Keystone, Supplier Part Number 1=36-5001-ND
T1: library part CMP-0086715-1, "EE19 16 Pin Transformer", Manufacturer=Bourns
TP3: library part CMP-0055139-1, "Test Point, Miniature, White, TH", Color=White, Manufacturer=Keystone, Supplier Part Number 1=36-5002-ND
TP12 TP19: library part CMP-0055140-1, "Test Point, Miniature, Orange, TH", Color=Orange, Manufacturer=Keystone, Supplier Part Number 1=36-5003-ND
U1: library part CMP-0081540-1, "Automotive Grade 2.2-MHz Wide Input Non-synchronous Boost Controller, DSS0012C (WSON-12)", Alternate Manufacturer="Texas Instruments", Alternate PartNumber=LM51551QDSSRQ1
U2: library part CMP-0006166-3, "Optocoupler, 3.75 kV, 80-160% CTR, SMT", Manufacturer=Vishay-Semiconductor, Supplier Part Number 1=TCMT1107CT-ND, Voltage_Isolation_Vrms=3.75kV
U3: library part CMP-0033164-1, "Automotive Catalog Adjustable Precision Shunt Regulator, 34 ppm / degC, 100 mA, -40 to 125 degC, 3-pin SOT-23 (DBZ), Green (RoHS & no Sb/Br)", Manufacturer="Texas Instruments", Rating=Automotive, Temp Coeff(Typ)(ppm/ degree C)=34

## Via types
v1: diameter 0.864, hole 0.406, Top Layer to Bottom Layer, 159 vias
v2: diameter 0.864, hole 0.406, Top Layer to Bottom Layer, tented top, 13 vias
v3: diameter 1.27, hole 0.711, Top Layer to Bottom Layer, 9 vias
v4: diameter 0.6, hole 0.3, Top Layer to Bottom Layer, 3 vias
